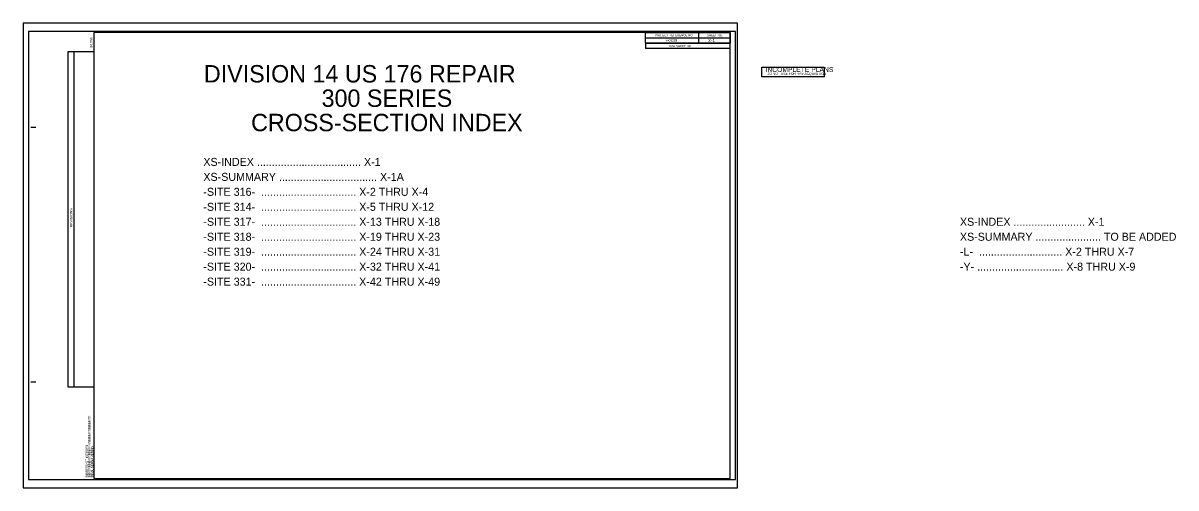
# Model space of a CAD drawing. Extents: x -5 to 538, y 254 to 473.
import ezdxf

# ---------------------------------------------------------------- set-up
doc = ezdxf.new("R2010")
doc.units = 0
for name, color, linetype in [('Prop DSN Text', 7, 'Continuous'), ('Prop XS Project Number', 7, 'Continuous'), ('Sheet Block Revision CELL', 7, 'Continuous'), ('Sheet Cutting Line CELL', 7, 'Continuous'), ('Sheet Data Field CELL', 7, 'Continuous'), ('Sheet Plan CELL', 7, 'Continuous'), ('Sheet Plot Border Inside CELL', 7, 'Continuous'), ('Sheet Plot Border Outside CELL', 7, 'Continuous'), ('Sheet Sticker Incomplete CELL', 7, 'Continuous')]:
    doc.layers.add(name, color=color, linetype=linetype)

msp = doc.modelspace()

# ---------------------------------------------------------------- linework, layer by layer
at = {"layer": 'Sheet Block Revision CELL'}
msp.add_line((19.24, 301.35), (19.24, 459.48), dxfattribs=at)
msp.add_lwpolyline([(16.33, 301.35), (16.33, 459.48), (28.44, 459.48), (28.44, 301.35)], close=True, dxfattribs=at)
at = {"layer": 'Sheet Cutting Line CELL'}
for p, q in [((331.84, 472.85), (-4.86, 472.85)), ((-4.86, 472.85), (-4.86, 253.85)), ((-4.86, 253.85), (331.84, 253.85))]:
    msp.add_line(p, q, dxfattribs=at)
at = {"layer": 'Sheet Plan CELL'}
for p, q in [((28.44, 468.35), (28.44, 468.35)), ((313.43, 468.34), (313.44, 463.34)), ((288.43, 465.84), (328.44, 465.84)), ((288.43, 463.34), (328.44, 463.34)), ((288.43, 463.34), (328.44, 463.34)), ((288.43, 463.34), (288.43, 460.84)), ((328.44, 460.84), (288.43, 460.84)), ((-1.26, 423.85), (1.24, 423.85)), ((-1.26, 303.85), (1.24, 303.85)), ((28.44, 258.35), (28.44, 258.35))]:
    msp.add_line(p, q, dxfattribs=at)
for points in [[(328.45, 468.35), (28.44, 468.35), (28.44, 258.35), (328.44, 258.35)], [(288.43, 468.35), (328.45, 468.35), (328.44, 463.34), (288.43, 463.34)]]:
    msp.add_lwpolyline(points, close=True, dxfattribs=at)
at = {"layer": 'Sheet Plot Border Inside CELL'}
msp.add_lwpolyline([(-2.26, 257.85), (330.94, 257.85), (330.94, 468.85), (-2.26, 468.85)], close=True, dxfattribs=at)
at = {"layer": 'Sheet Plot Border Outside CELL'}
msp.add_lwpolyline([(-4.86, 253.85), (331.84, 253.85), (331.84, 472.85), (-4.86, 472.85)], close=True, dxfattribs=at)
at = {"layer": 'Sheet Sticker Incomplete CELL'}
msp.add_lwpolyline([(343.26, 447.45), (343.26, 452.15), (372.66, 452.15), (372.66, 447.45)], close=True, dxfattribs=at)

# ---------------------------------------------------------------- texts
at = {"layer": 'Prop DSN Text'}
for s, height, p in [('DIVISION 14 US 176 REPAIR', 8.2021, (80.37, 444.86)), ('300 SERIES', 8.202, (135.84, 433.37)), ('CROSS-SECTION INDEX', 8.2021, (102.61, 421.89)), ('XS-INDEX ................................... X-1', 3.773, (80.11, 405.56)), ('XS-SUMMARY ................................. X-1A', 3.773, (80.11, 398.51)), ('-SITE 316-  ................................ X-2 THRU X-4', 3.773, (80.11, 391.46)), ('-SITE 314-  ................................ X-5 THRU X-12', 3.773, (80.11, 384.4)), ('-SITE 317-  ................................ X-13 THRU X-18', 3.773, (80.11, 377.35)), ('XS-INDEX ........................ X-1', 3.773, (436.67, 377.36)), ('-SITE 318-  ................................ X-19 THRU X-23', 3.773, (80.11, 370.29)), ('XS-SUMMARY ...................... TO BE ADDED', 3.773, (436.67, 370.3)), ('-SITE 319-  ................................ X-24 THRU X-31', 3.773, (80.11, 363.24)), ('-L-  ............................ X-2 THRU X-7', 3.773, (436.67, 363.25)), ('-SITE 320-  ................................ X-32 THRU X-41', 3.773, (80.11, 356.19)), ('-Y- ............................. X-8 THRU X-9', 3.773, (436.67, 356.19)), ('-SITE 331-  ................................ X-42 THRU X-49', 3.773, (80.11, 349.13))]:
    msp.add_text(s, height=height, dxfattribs=at).set_placement(p)
at = {"layer": 'Prop XS Project Number'}
msp.add_text('W03293', height=1.05, dxfattribs=at).set_placement((298.03, 464.15))
at = {"layer": 'Sheet Block Revision CELL'}
msp.add_text('REVISIONS', height=1.2, rotation=90, dxfattribs=at).set_placement((18.43, 376.58))
at = {"layer": 'Sheet Data Field CELL'}
msp.add_text('   X-1   ', height=1.5, rotation=0, dxfattribs=at).set_placement((316.23, 463.9))
at = {"layer": 'Sheet Plan CELL'}
for s, height, rotation, p in [('PROJECT REFERENCE NO.', 1, 0, (292.87, 466.61)), ('SHEET NO.', 1, 0, (317.5, 466.59)), ('8/17/99', 1.05, 90, (27.79, 461.31)), ('R/W SHEET NO.', 1, 0, (299.83, 461.5)), ('$$$$$$$$$$$$$$$$DGN$$$$$$$$$$$$$$$$', 1.05, 90, (26.91, 258.82)), ('$$$$$$SYSTIME$$$$$', 1.05, 90, (25.7, 258.82)), ('$$$$USERNAME$$$$', 1.05, 90, (28.22, 258.83))]:
    msp.add_text(s, height=height, rotation=rotation, dxfattribs=at).set_placement(p)
at = {"layer": 'Sheet Sticker Incomplete CELL'}
for s, height, p in [('INCOMPLETE PLANS', 2.304, (345.05, 449.79)), ('DO NOT USE FOR R/W ACQUISITION', 1.152, (345.7, 448.4))]:
    msp.add_text(s, height=height, dxfattribs=at).set_placement(p)

doc.saveas('drawing.dxf')
